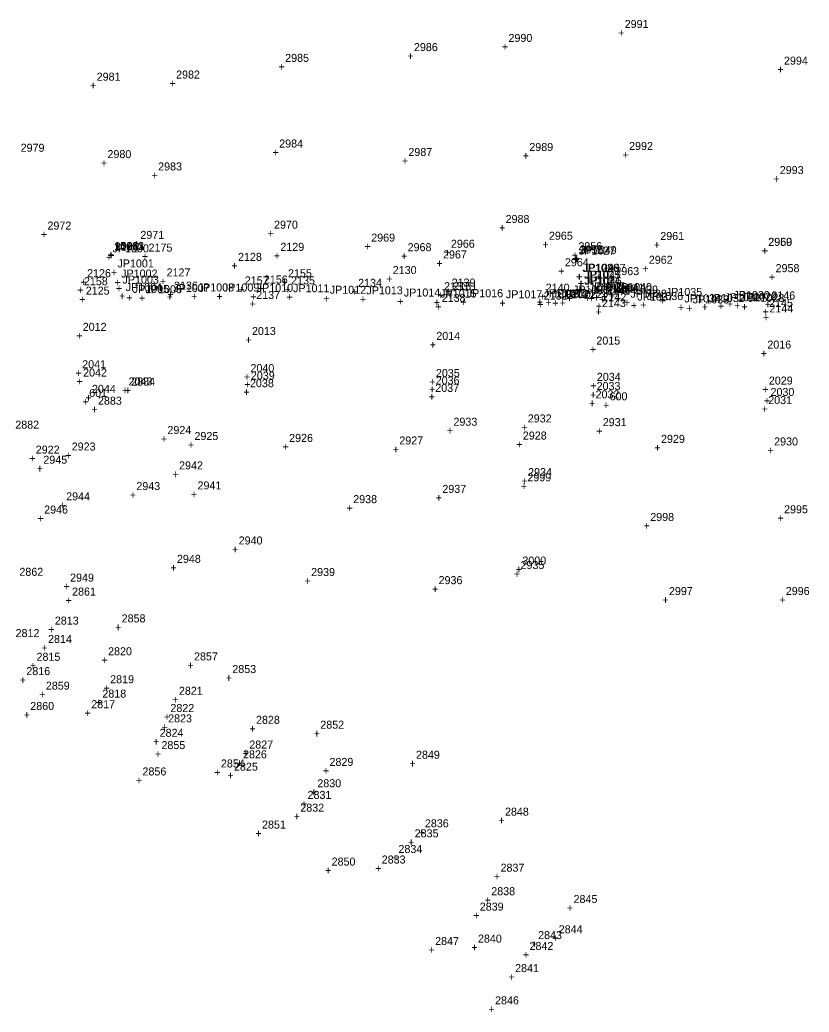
# Model space of a CAD drawing. Extents: x 2192192 to 2193475, y 863716 to 864270.
# Drawn here: x 2192729.4 to 2192975.6, y 863715.6 to 864025.4 of the extents above; entities that cross this region are included whole.
import ezdxf

# ---------------------------------------------------------------- set-up
doc = ezdxf.new("R2010")
doc.units = 0
for name, color, linetype in [('S_Control_Survey_Traverse_Chek', 7, 'Continuous'), ('S_Control_Temp_Traverse', 7, 'Continuous'), ('S_Drainage_Ditch_Line', 7, 'Continuous'), ('S_Drainage_Waterway', 7, 'Continuous'), ('S_Ground_Elevation', 7, 'Continuous'), ('S_Ground_LevelString', 7, 'Continuous'), ('S_Ground_SpotElevation', 7, 'Continuous'), ('S_Guardrail_Beam', 7, 'Continuous'), ('S_Property_RockBoulder', 7, 'Continuous'), ('S_Roadway_Centerline', 7, 'Continuous'), ('S_Roadway_Drive_Gravel', 7, 'Continuous'), ('S_Roadway_Edge_Pavement', 7, 'Continuous'), ('S_Roadway_Edge_Shoulder', 7, 'Continuous'), ('S_Roadway_Edge_TW', 7, 'Continuous'), ('S_Traffic_JunctionBox', 7, 'Continuous'), ('S_Traffic_Sign_SinglePost', 7, 'Continuous'), ('S_Trees_TreeLine', 7, 'Continuous'), ('S_Utilities_GuyWire3', 7, 'Continuous'), ('S_Utilities_Pole_Power', 7, 'Continuous'), ('S_Utilities_UG_Telephone', 7, 'Continuous')]:
    doc.layers.add(name, color=color, linetype=linetype)

msp = doc.modelspace()

# ---------------------------------------------------------------- texts
at = {"layer": 'S_Control_Survey_Traverse_Chek'}
for s, p in [('1009', (2192758.82, 863953.45)), ('1008', (2192758.92, 863953.57)), ('+', (2192756.75, 863950.7)), ('+', (2192756.86, 863950.82))]:
    msp.add_text(s, height=2.5, dxfattribs=at).set_placement(p)
at = {"layer": 'S_Control_Temp_Traverse'}
for s, p in [('151_3', (2192758.8, 863953.56)), ('151_2', (2192758.8, 863953.56)), ('151', (2192758.8, 863953.56)), ('151_1', (2192758.8, 863953.56)), ('+', (2192756.74, 863950.81)), ('+', (2192756.74, 863950.81)), ('+', (2192756.74, 863950.81)), ('+', (2192756.74, 863950.81)), ('601', (2192751.01, 863907.67)), ('601', (2192751.01, 863907.67)), ('601', (2192751.01, 863907.67)), ('600', (2192913.38, 863906.62)), ('600', (2192913.38, 863906.62)), ('600', (2192913.38, 863906.62)), ('+', (2192748.95, 863904.92)), ('+', (2192748.95, 863904.92)), ('+', (2192748.95, 863904.92)), ('+', (2192911.32, 863903.87)), ('+', (2192911.32, 863903.87)), ('+', (2192911.32, 863903.87))]:
    msp.add_text(s, height=2.5, dxfattribs=at).set_placement(p)
at = {"layer": 'S_Drainage_Ditch_Line'}
for s, p in [('2968', (2192850.37, 863953.18)), ('+', (2192848.31, 863950.43)), ('2967', (2192861.41, 863950.9)), ('+', (2192859.35, 863948.15)), ('2964', (2192899.44, 863948.47)), ('2962', (2192925.62, 863949.25)), ('2958', (2192965.18, 863946.63)), ('+', (2192897.38, 863945.72)), ('2963', (2192915.18, 863945.71)), ('+', (2192923.56, 863946.5)), ('+', (2192963.11, 863943.88)), ('+', (2192913.12, 863942.96)), ('2933', (2192864.67, 863898.68)), ('2932', (2192887.86, 863899.71)), ('2931', (2192911.25, 863898.55)), ('+', (2192862.61, 863895.93)), ('+', (2192885.8, 863896.96)), ('+', (2192909.19, 863895.8))]:
    msp.add_text(s, height=2.5, dxfattribs=at).set_placement(p)
at = {"layer": 'S_Drainage_Waterway'}
for s, p in [('2828', (2192803.06, 863805.61)), ('+', (2192801, 863802.86))]:
    msp.add_text(s, height=2.5, dxfattribs=at).set_placement(p)
at = {"layer": 'S_Ground_Elevation'}
for s, p in [('2991', (2192918.1, 864022.87)), ('2990', (2192881.84, 864018.52)), ('+', (2192916.04, 864020.12)), ('2986', (2192852.34, 864015.65)), ('+', (2192879.78, 864015.77)), ('2985', (2192812.16, 864012.29)), ('+', (2192850.28, 864012.9)), ('2994', (2192967.8, 864011.43)), ('+', (2192810.1, 864009.54)), ('2981', (2192753.34, 864006.41)), ('2982', (2192778.12, 864007.09)), ('+', (2192965.74, 864008.68)), ('+', (2192751.28, 864003.66)), ('+', (2192776.06, 864004.34)), ('2979', (2192729.63, 863984.23)), ('2984', (2192810.3, 863985.55)), ('2989', (2192888.34, 863984.47)), ('2992', (2192919.47, 863984.78)), ('2980', (2192756.72, 863982.24)), ('+', (2192808.24, 863982.8)), ('2987', (2192850.61, 863982.9)), ('+', (2192886.28, 863981.72)), ('+', (2192917.41, 863982.03)), ('+', (2192754.66, 863979.49)), ('2983', (2192772.53, 863978.39)), ('+', (2192848.55, 863980.15)), ('+', (2192770.47, 863975.64)), ('2993', (2192966.49, 863977.26)), ('+', (2192964.43, 863974.51)), ('2972', (2192738, 863959.93)), ('2970', (2192808.69, 863960.21)), ('+', (2192735.94, 863957.18)), ('2971', (2192766.98, 863957.02)), ('+', (2192806.63, 863957.46)), ('2969', (2192839.01, 863956.17)), ('2965', (2192894.46, 863956.76)), ('2961', (2192929.2, 863956.67)), ('+', (2192764.91, 863954.27)), ('+', (2192836.95, 863953.42)), ('2966', (2192863.88, 863954.25)), ('+', (2192892.4, 863954.01)), ('+', (2192927.14, 863953.92)), ('2959', (2192962.88, 863954.84)), ('+', (2192861.82, 863951.5)), ('+', (2192960.82, 863952.09)), ('2924', (2192775.43, 863896.09)), ('2925', (2192783.86, 863894.22)), ('2926', (2192813.4, 863893.63)), ('2928', (2192886.32, 863894.37)), ('2923', (2192745.56, 863890.95)), ('+', (2192773.37, 863893.34)), ('+', (2192781.8, 863891.47)), ('2927', (2192847.78, 863892.84)), ('+', (2192884.26, 863891.62)), ('2929', (2192929.43, 863893.34)), ('2930', (2192964.73, 863892.53)), ('2922', (2192734.34, 863889.98)), ('+', (2192743.5, 863888.2)), ('+', (2192811.34, 863890.88)), ('+', (2192845.72, 863890.09)), ('+', (2192927.36, 863890.59)), ('+', (2192962.67, 863889.78)), ('+', (2192732.28, 863887.23)), ('2945', (2192736.71, 863886.82)), ('2942', (2192779.06, 863885.05)), ('+', (2192734.65, 863884.07)), ('+', (2192777, 863882.3)), ('2999', (2192887.73, 863881.33)), ('2934', (2192887.96, 863882.95)), ('2943', (2192765.73, 863878.59)), ('2941', (2192784.81, 863878.8)), ('+', (2192885.67, 863878.58)), ('+', (2192885.89, 863880.2)), ('2944', (2192743.83, 863875.39)), ('+', (2192763.67, 863875.84)), ('+', (2192782.75, 863876.05)), ('2937', (2192861.2, 863877.71)), ('+', (2192741.77, 863872.64)), ('2938', (2192833.39, 863874.51)), ('+', (2192859.14, 863874.96)), ('2946', (2192736.96, 863871.26)), ('+', (2192831.33, 863871.76)), ('2998', (2192926.07, 863868.95)), ('2995', (2192967.83, 863871.34)), ('+', (2192734.9, 863868.51)), ('+', (2192924.01, 863866.2)), ('+', (2192965.77, 863868.59)), ('2940', (2192797.65, 863861.61)), ('+', (2192795.59, 863858.86)), ('2948', (2192778.39, 863855.87)), ('2935', (2192885.59, 863853.93)), ('3000', (2192886.16, 863855.34)), ('2862', (2192729.23, 863851.82)), ('+', (2192776.33, 863853.12)), ('2939', (2192820.27, 863851.75)), ('+', (2192883.53, 863851.18)), ('+', (2192884.1, 863852.59)), ('2949', (2192745.05, 863850.01)), ('+', (2192818.2, 863849)), ('2936', (2192860.03, 863849.22)), ('+', (2192742.99, 863847.26)), ('2861', (2192745.68, 863845.65)), ('+', (2192857.97, 863846.47)), ('2997', (2192931.9, 863845.81)), ('2996', (2192968.36, 863845.83)), ('+', (2192743.62, 863842.9)), ('+', (2192929.84, 863843.06)), ('+', (2192966.29, 863843.08)), ('2858', (2192761.14, 863837.28)), ('+', (2192759.08, 863834.53)), ('2857', (2192783.73, 863825.41)), ('+', (2192781.66, 863822.66)), ('2853', (2192795.67, 863821.46)), ('2859', (2192737.49, 863816.28)), ('+', (2192793.61, 863818.71)), ('+', (2192735.42, 863813.53)), ('2860', (2192732.63, 863809.92)), ('+', (2192730.57, 863807.17)), ('2852', (2192823.12, 863804.08)), ('+', (2192821.06, 863801.33)), ('2855', (2192773.56, 863797.72)), ('+', (2192771.5, 863794.97)), ('2849', (2192852.98, 863794.71)), ('2854', (2192792.11, 863791.98)), ('+', (2192850.92, 863791.96)), ('2856', (2192767.64, 863789.49)), ('+', (2192790.05, 863789.23)), ('+', (2192765.58, 863786.74)), ('2848', (2192880.74, 863776.94)), ('2851', (2192804.93, 863772.9)), ('+', (2192878.68, 863774.19)), ('+', (2192802.87, 863770.15)), ('2850', (2192826.65, 863761.35)), ('+', (2192824.59, 863758.6)), ('2845', (2192902.14, 863749.65)), ('+', (2192900.08, 863746.9)), ('2847', (2192858.95, 863736.55)), ('+', (2192856.89, 863733.8)), ('2846', (2192877.65, 863718.02)), ('+', (2192875.58, 863715.27))]:
    msp.add_text(s, height=2.5, dxfattribs=at).set_placement(p)
at = {"layer": 'S_Ground_LevelString'}
for s, p in [('2136', (2192777.48, 863941.18)), ('2135', (2192814.02, 863942.81)), ('2134', (2192834.91, 863942.05)), ('2133', (2192861.76, 863941)), ('+', (2192775.42, 863938.43)), ('+', (2192811.96, 863940.06)), ('+', (2192832.84, 863939.3)), ('+', (2192859.7, 863938.25))]:
    msp.add_text(s, height=2.5, dxfattribs=at).set_placement(p)
at = {"layer": 'S_Ground_SpotElevation'}
for s, p in [('2812', (2192728.05, 863832.69)), ('2814', (2192738.17, 863830.85)), ('+', (2192736.11, 863828.1)), ('2815', (2192734.58, 863825.29)), ('+', (2192732.52, 863822.54)), ('2819', (2192757.56, 863818.27)), ('2818', (2192755.12, 863813.79)), ('+', (2192755.5, 863815.52)), ('+', (2192753.06, 863811.04)), ('2822', (2192776.35, 863809.29)), ('+', (2192774.29, 863806.54)), ('2823', (2192775.64, 863806.06)), ('+', (2192773.58, 863803.31)), ('2827', (2192800.97, 863797.89)), ('+', (2192798.91, 863795.14)), ('2826', (2192799.01, 863794.84)), ('+', (2192796.95, 863792.09)), ('2830', (2192822.2, 863785.81)), ('2831', (2192819.15, 863782.18)), ('+', (2192820.14, 863783.06)), ('+', (2192817.09, 863779.43)), ('2835', (2192852.57, 863770.17)), ('+', (2192850.51, 863767.42)), ('2834', (2192847.51, 863765.28)), ('+', (2192845.45, 863762.53)), ('2838', (2192876.46, 863752.1)), ('+', (2192874.4, 863749.35)), ('2839', (2192872.88, 863747.29)), ('+', (2192870.82, 863744.54)), ('2843', (2192891.08, 863738.4)), ('2842', (2192888.4, 863735.01)), ('+', (2192889.02, 863735.65)), ('+', (2192886.34, 863732.26))]:
    msp.add_text(s, height=2.5, dxfattribs=at).set_placement(p)
at = {"layer": 'S_Guardrail_Beam'}
for s, p in [('2155', (2192813.04, 863945.05)), ('2158', (2192749.36, 863942.54)), ('2157', (2192799.56, 863942.8)), ('2156', (2192805.52, 863943.09)), ('+', (2192810.98, 863942.3)), ('+', (2192747.3, 863939.79)), ('+', (2192797.5, 863940.05)), ('+', (2192803.46, 863940.34))]:
    msp.add_text(s, height=2.5, dxfattribs=at).set_placement(p)
at = {"layer": 'S_Property_RockBoulder'}
for s, p in [('2988', (2192880.94, 863961.99)), ('+', (2192878.88, 863959.24)), ('2957', (2192910.93, 863946.72)), ('+', (2192908.87, 863943.97))]:
    msp.add_text(s, height=2.5, dxfattribs=at).set_placement(p)
at = {"layer": 'S_Roadway_Centerline'}
for s, p in [('2012', (2192749, 863928.31)), ('+', (2192746.94, 863925.56)), ('2013', (2192801.8, 863927.01)), ('2014', (2192859.32, 863925.5)), ('+', (2192799.74, 863924.26)), ('+', (2192857.26, 863922.75)), ('2015', (2192909.26, 863924.02)), ('2016', (2192962.6, 863922.77)), ('+', (2192907.2, 863921.27)), ('+', (2192960.54, 863920.02))]:
    msp.add_text(s, height=2.5, dxfattribs=at).set_placement(p)
at = {"layer": 'S_Roadway_Drive_Gravel'}
for s, p in [('2884', (2192764.14, 863911.23)), ('+', (2192762.08, 863908.48)), ('2883', (2192753.75, 863905.25)), ('+', (2192751.69, 863902.5)), ('2882', (2192727.95, 863897.76))]:
    msp.add_text(s, height=2.5, dxfattribs=at).set_placement(p)
at = {"layer": 'S_Roadway_Edge_Pavement'}
for s, p in [('2129', (2192810.66, 863953.29)), ('2128', (2192797.45, 863950.16)), ('+', (2192808.6, 863950.54)), ('+', (2192795.39, 863947.41)), ('2126', (2192750.35, 863945.06)), ('2127', (2192775.15, 863945.3)), ('2130', (2192845.73, 863946.04)), ('+', (2192748.28, 863942.31)), ('+', (2192773.09, 863942.55)), ('+', (2192843.67, 863943.29)), ('2131', (2192864.66, 863941.06)), ('+', (2192862.6, 863938.31)), ('2132', (2192892.84, 863938.09)), ('2142', (2192911.13, 863937.56)), ('+', (2192890.78, 863935.34)), ('+', (2192909.07, 863934.81)), ('2145', (2192963.17, 863935.78)), ('+', (2192961.1, 863933.03)), ('2042', (2192749.11, 863914.04)), ('2039', (2192801.46, 863913.09)), ('+', (2192747.05, 863911.29)), ('+', (2192799.4, 863910.34)), ('2036', (2192859.13, 863911.57)), ('2033', (2192909.34, 863909.84)), ('+', (2192857.06, 863908.82)), ('+', (2192907.27, 863907.09)), ('2030', (2192963.6, 863907.98)), ('+', (2192961.54, 863905.23))]:
    msp.add_text(s, height=2.5, dxfattribs=at).set_placement(p)
at = {"layer": 'S_Roadway_Edge_Shoulder'}
for s, p in [('2139', (2192864.12, 863942.14)), ('2140', (2192893.47, 863940.53)), ('+', (2192862.05, 863939.39)), ('+', (2192891.41, 863937.78)), ('2141', (2192912.22, 863939.57)), ('2146', (2192963.86, 863938.11)), ('+', (2192910.15, 863936.82)), ('+', (2192961.79, 863935.36)), ('2043', (2192763.3, 863911.28)), ('2038', (2192801.18, 863910.71)), ('2037', (2192859, 863909.25)), ('2044', (2192751.88, 863908.95)), ('+', (2192761.24, 863908.53)), ('+', (2192799.12, 863907.96)), ('+', (2192856.94, 863906.5)), ('2032', (2192909.02, 863907.22)), ('+', (2192749.82, 863906.2)), ('+', (2192906.96, 863904.47)), ('2031', (2192962.89, 863905.43)), ('+', (2192960.83, 863902.68))]:
    msp.add_text(s, height=2.5, dxfattribs=at).set_placement(p)
at = {"layer": 'S_Roadway_Edge_TW'}
for s, p in [('2125', (2192749.94, 863939.62)), ('2137', (2192803.12, 863938.25)), ('2138', (2192861.02, 863937.35)), ('+', (2192747.88, 863936.87)), ('+', (2192801.06, 863935.5)), ('+', (2192858.96, 863934.6)), ('2143', (2192911, 863935.74)), ('2144', (2192963.25, 863934.07)), ('+', (2192908.94, 863932.99)), ('+', (2192961.19, 863931.32)), ('2041', (2192748.83, 863916.63)), ('2040', (2192801.33, 863915.44)), ('+', (2192746.76, 863913.88)), ('+', (2192799.27, 863912.69)), ('2035', (2192859.19, 863913.9)), ('2034', (2192909.4, 863912.7)), ('+', (2192857.13, 863911.15)), ('+', (2192907.34, 863909.95)), ('2029', (2192963.07, 863911.53)), ('+', (2192961.01, 863908.78))]:
    msp.add_text(s, height=2.5, dxfattribs=at).set_placement(p)
at = {"layer": 'S_Traffic_JunctionBox'}
for s, p in [('2955', (2192904, 863952.48)), ('+', (2192901.94, 863949.73))]:
    msp.add_text(s, height=2.5, dxfattribs=at).set_placement(p)
at = {"layer": 'S_Traffic_Sign_SinglePost'}
for s, p in [('2956', (2192903.64, 863953.49)), ('+', (2192901.58, 863950.74))]:
    msp.add_text(s, height=2.5, dxfattribs=at).set_placement(p)
at = {"layer": 'S_Trees_TreeLine'}
for s, p in [('2960', (2192962.93, 863954.85)), ('+', (2192960.87, 863952.1)), ('2813', (2192740.29, 863836.59)), ('+', (2192738.22, 863833.84)), ('2820', (2192756.91, 863827.02)), ('+', (2192754.85, 863824.27)), ('2816', (2192731.4, 863820.82)), ('+', (2192729.34, 863818.07)), ('2821', (2192779, 863814.68)), ('2817', (2192751.65, 863810.48)), ('+', (2192776.93, 863811.93)), ('+', (2192749.59, 863807.73)), ('2824', (2192772.99, 863801.57)), ('+', (2192770.93, 863798.82)), ('2829', (2192825.99, 863792.47)), ('2825', (2192796.19, 863790.99)), ('+', (2192823.93, 863789.72)), ('+', (2192794.13, 863788.24)), ('2832', (2192816.89, 863778.18)), ('+', (2192814.83, 863775.43)), ('2836', (2192855.75, 863773.29)), ('+', (2192853.69, 863770.54)), ('2833', (2192842.29, 863761.99)), ('+', (2192840.23, 863759.24)), ('2837', (2192879.36, 863759.44)), ('+', (2192877.3, 863756.69)), ('2844', (2192897.51, 863740.21)), ('2840', (2192872.31, 863737.31)), ('+', (2192895.45, 863737.46)), ('+', (2192870.25, 863734.56)), ('2841', (2192883.91, 863728.1)), ('+', (2192881.85, 863725.35))]:
    msp.add_text(s, height=2.5, dxfattribs=at).set_placement(p)
at = {"layer": 'S_Utilities_GuyWire3'}
for s, p in [('2175', (2192769.53, 863953.05)), ('+', (2192767.47, 863950.3))]:
    msp.add_text(s, height=2.5, dxfattribs=at).set_placement(p)
at = {"layer": 'S_Utilities_Pole_Power'}
for s, p in [('2174', (2192758.99, 863953.38)), ('+', (2192756.92, 863950.63))]:
    msp.add_text(s, height=2.5, dxfattribs=at).set_placement(p)
at = {"layer": 'S_Utilities_UG_Telephone'}
for s, p in [('JP1000', (2192758.3, 863952.82)), ('+', (2192756.24, 863950.07)), ('JP1027', (2192903.77, 863952.14)), ('JP1049', (2192904.26, 863952.27)), ('JP1001', (2192759.83, 863948.11)), ('+', (2192901.71, 863949.39)), ('+', (2192902.2, 863949.52)), ('JP1026', (2192904.93, 863946.7)), ('JP1048', (2192905.16, 863946.76)), ('+', (2192757.77, 863945.36)), ('JP1002', (2192760.99, 863944.94)), ('+', (2192902.87, 863943.95)), ('+', (2192903.1, 863944.01)), ('JP1025', (2192905.42, 863944.59)), ('JP1047', (2192905.62, 863944.63)), ('+', (2192758.93, 863942.19)), ('JP1003', (2192761.42, 863943.06)), ('JP1004', (2192762.4, 863940.71)), ('JP1005', (2192764.6, 863940.17)), ('JP1007', (2192777.26, 863940.44)), ('JP1008', (2192784.87, 863940.62)), ('JP1009', (2192792.74, 863940.59)), ('JP1010', (2192803.3, 863940.49)), ('JP1011', (2192814.62, 863940.37)), ('+', (2192903.36, 863941.84)), ('+', (2192903.55, 863941.88)), ('JP1024', (2192905.45, 863942.77)), ('JP1046', (2192905.77, 863942.74)), ('JP1045', (2192906.93, 863940.96)), ('JP1042', (2192910.38, 863940.26)), ('JP1041', (2192912.88, 863940.57)), ('JP1040', (2192915.26, 863940.74)), ('+', (2192759.36, 863940.31)), ('+', (2192760.34, 863937.96)), ('JP1006', (2192768.61, 863940.05)), ('+', (2192775.2, 863937.69)), ('+', (2192782.81, 863937.87)), ('+', (2192790.68, 863937.84)), ('+', (2192801.24, 863937.74)), ('+', (2192812.56, 863937.62)), ('JP1012', (2192826.08, 863939.89)), ('JP1013', (2192837.5, 863939.71)), ('JP1014', (2192849.2, 863939.03)), ('JP1015', (2192860.55, 863938.72)), ('JP1016', (2192868.82, 863938.8)), ('JP1017', (2192881.04, 863938.47)), ('JP1018', (2192892.7, 863938.81)), ('JP1019', (2192895.39, 863938.73)), ('JP1021', (2192897.54, 863938.49)), ('JP1022', (2192899.86, 863938.56)), ('JP1023', (2192901.97, 863939.93)), ('+', (2192903.39, 863940.02)), ('+', (2192903.71, 863939.99)), ('+', (2192904.87, 863938.21)), ('JP1044', (2192907.54, 863940.02)), ('+', (2192908.32, 863937.51)), ('JP1043', (2192908.78, 863939.92)), ('+', (2192910.82, 863937.82)), ('+', (2192913.2, 863937.99)), ('JP1039', (2192917.15, 863939.96)), ('JP1038', (2192919.92, 863938.65)), ('JP1037', (2192922.05, 863937.78)), ('JP1036', (2192925, 863937.93)), ('JP1035', (2192930.94, 863939.21)), ('JP1034', (2192936.76, 863937.19)), ('JP1032', (2192944.21, 863937.3)), ('JP1031', (2192949.23, 863937.57)), ('JP1030', (2192952.05, 863938.25)), ('JP1029', (2192954.29, 863937.73)), ('JP1028', (2192956.55, 863937.37)), ('+', (2192762.54, 863937.42)), ('+', (2192766.54, 863937.3)), ('+', (2192824.02, 863937.14)), ('+', (2192835.44, 863936.96)), ('+', (2192847.14, 863936.28)), ('+', (2192858.49, 863935.97)), ('+', (2192866.76, 863936.05)), ('+', (2192878.98, 863935.72)), ('+', (2192890.64, 863936.06)), ('+', (2192893.33, 863935.98)), ('+', (2192895.48, 863935.74)), ('+', (2192897.8, 863935.81)), ('+', (2192899.91, 863937.18)), ('+', (2192905.48, 863937.27)), ('+', (2192906.72, 863937.17)), ('+', (2192915.08, 863937.22)), ('+', (2192917.86, 863935.9)), ('+', (2192919.99, 863935.03)), ('+', (2192922.93, 863935.18)), ('+', (2192928.88, 863936.46)), ('+', (2192934.7, 863934.44)), ('JP1033', (2192939.32, 863936.87)), ('+', (2192942.14, 863934.55)), ('+', (2192947.17, 863934.82)), ('+', (2192949.99, 863935.5)), ('+', (2192952.23, 863934.98)), ('+', (2192954.49, 863934.62)), ('+', (2192937.26, 863934.13))]:
    msp.add_text(s, height=2.5, dxfattribs=at).set_placement(p)

doc.saveas('drawing.dxf')
